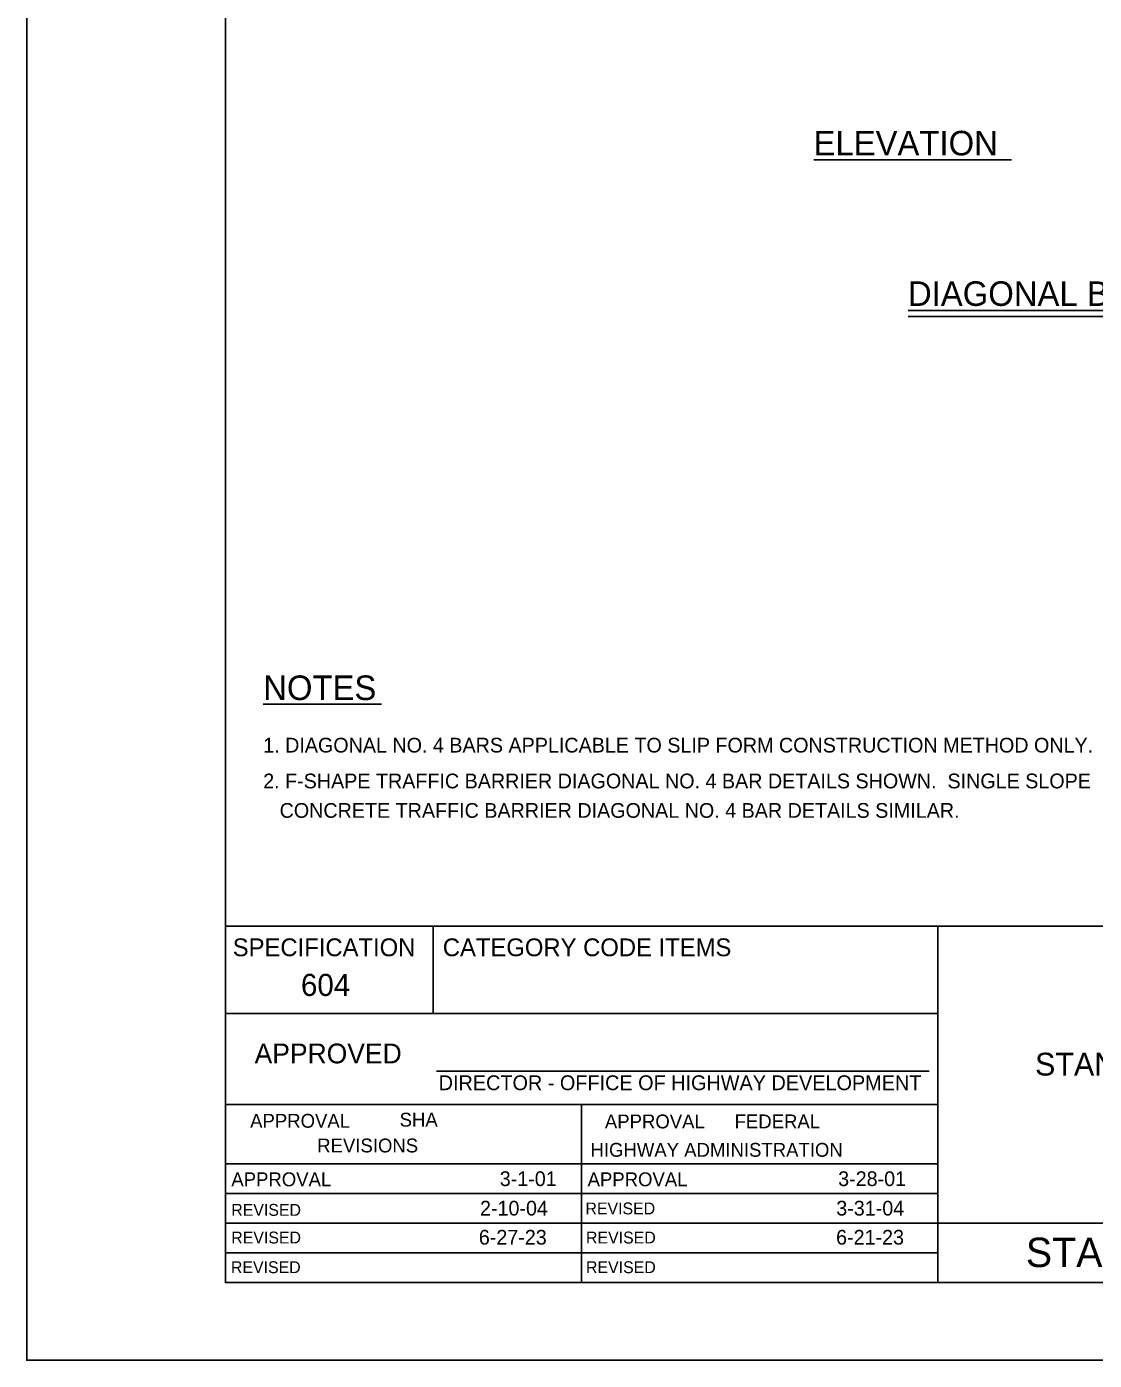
# Model space of a CAD drawing. Extents: x -111.7 to -103.2, y -200 to -189.
# Drawn here: x -111.73 to -107.38, y -199.99 to -194.55 of the extents above; entities that cross this region are included whole.
import ezdxf

# ---------------------------------------------------------------- set-up
doc = ezdxf.new("R2010")
doc.units = 0
for name, color, linetype in [('BORD-LINE', 7, 'Continuous'), ('Level 12', 7, 'Continuous'), ('Level 13', 7, 'Continuous'), ('TTLB-TEXT', 7, 'Continuous'), ('USER-CLIP', 7, 'Continuous')]:
    doc.layers.add(name, color=color, linetype=linetype)

msp = doc.modelspace()

# ---------------------------------------------------------------- linework, layer by layer
at = {"layer": 'BORD-LINE'}
for p, q in [((-108.0217, -198.2184), (-110.923, -198.2184)), ((-110.0768, -198.5731), (-110.0768, -198.2184)), ((-108.0217, -199.6692), (-108.0217, -198.2184)), ((-103.5488, -198.2184), (-108.0217, -198.2184)), ((-110.923, -198.5731), (-108.0217, -198.5731)), ((-110.0638, -198.8082), (-108.0569, -198.8082)), ((-110.923, -198.9438), (-110.0768, -198.9438)), ((-110.923, -199.6692), (-110.923, -198.9438)), ((-110.923, -198.9438), (-108.0217, -198.9438)), ((-109.4724, -198.9438), (-109.4724, -199.6692)), ((-110.923, -199.1856), (-108.0217, -199.1856)), ((-110.923, -199.3065), (-108.0217, -199.3065)), ((-110.923, -199.4274), (-108.0217, -199.4274)), ((-108.0217, -199.4274), (-103.5488, -199.4274)), ((-110.923, -199.5483), (-108.0217, -199.5483)), ((-110.0768, -199.5483), (-108.0217, -199.5483))]:
    msp.add_line(p, q, dxfattribs=at)
msp.add_lwpolyline([(-110.923, -189.3161), (-103.5488, -189.3161), (-103.5488, -199.6692), (-110.923, -199.6692)], close=True, dxfattribs=at)
at = {"layer": 'Level 12'}
for p, q in [((-108.5269, -195.0978), (-107.7224, -195.0978)), ((-108.1425, -195.7107), (-106.3207, -195.7107)), ((-108.1425, -195.7357), (-106.3207, -195.7357))]:
    msp.add_line(p, q, dxfattribs=at)
at = {"layer": 'Level 13'}
msp.add_line((-110.7688, -197.3143), (-110.2865, -197.3143), dxfattribs=at)
at = {"layer": 'USER-CLIP'}
msp.add_lwpolyline([(-103.2319, -188.9861), (-111.7319, -188.9861), (-111.7319, -199.9861), (-103.2319, -199.9861)], close=True, dxfattribs=at)

# ---------------------------------------------------------------- texts
at = {"layer": 'Level 12'}
for s, p in [('ELEVATION', (-108.528, -195.0792)), ('DIAGONAL BAR DETAILS', (-108.1434, -195.6921))]:
    msp.add_text(s, height=0.1, dxfattribs=at).set_placement(p)
at = {"layer": 'Level 13'}
for s, height, p in [('NOTES', 0.1, (-110.7688, -197.2971)), ('1. DIAGONAL NO. 4 BARS APPLICABLE TO SLIP FORM CONSTRUCTION METHOD ONLY.', 0.06, (-110.7688, -197.5109)), ('2. F-SHAPE TRAFFIC BARRIER DIAGONAL NO. 4 BAR DETAILS SHOWN.  SINGLE SLOPE', 0.06, (-110.7689, -197.6568)), ('   CONCRETE TRAFFIC BARRIER DIAGONAL NO. 4 BAR DETAILS SIMILAR.', 0.06, (-110.7689, -197.7768)), ('604', 0.09, (-110.6152, -198.5023)), ('3-1-01', 0.06, (-109.8057, -199.2765)), ('3-28-01', 0.06, (-108.4277, -199.2765)), ('2-10-04', 0.06, (-109.886, -199.3965)), ('3-31-04', 0.06, (-108.4353, -199.3965)), ('6-27-23', 0.06, (-109.8908, -199.5149)), ('6-21-23', 0.06, (-108.4361, -199.5149))]:
    msp.add_text(s, height=height, dxfattribs=at).set_placement(p)
at = {"layer": 'TTLB-TEXT'}
for s, height, p in [('SPECIFICATION', 0.07254, (-110.8929, -198.3405)), ('CATEGORY CODE ITEMS ', 0.07254, (-110.0375, -198.3405)), ('APPROVED', 0.0806, (-110.8038, -198.7768)), ('STANDARDS FOR HIGHWAYS AND INCIDENTAL STRUCTURES', 0.09269, (-107.6259, -198.8264)), ('DIRECTOR - OFFICE OF HIGHWAY DEVELOPMENT', 0.0604, (-110.0543, -198.886)), ('APPROVAL', 0.05642, (-110.822, -199.039)), ('SHA', 0.05642, (-110.2134, -199.0343)), ('APPROVAL', 0.05642, (-109.3775, -199.0415)), ('FEDERAL', 0.05642, (-108.8494, -199.0414)), ('REVISIONS', 0.05642, (-110.5489, -199.1395)), ('HIGHWAY ADMINISTRATION', 0.05642, (-109.436, -199.1572)), ('APPROVAL', 0.05642, (-110.8986, -199.2772)), ('APPROVAL', 0.05642, (-109.448, -199.2772)), ('REVISED', 0.04836, (-110.8989, -199.3977)), ('REVISED', 0.04836, (-109.4567, -199.3918)), ('REVISED', 0.04836, (-110.8989, -199.5103)), ('REVISED', 0.04836, (-109.4544, -199.5103)), ('STANDARD NO.', 0.12, (-107.6635, -199.6064)), ('REVISED', 0.04836, (-110.9002, -199.6311)), ('REVISED', 0.04836, (-109.4544, -199.6311))]:
    msp.add_text(s, height=height, dxfattribs=at).set_placement(p)

doc.saveas('drawing.dxf')
